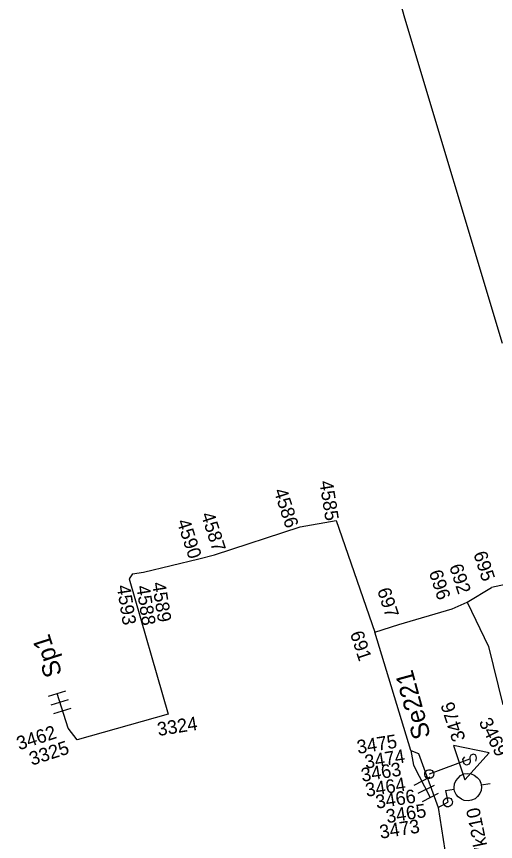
# Model space of a CAD drawing. Extents: x -535557 to -534097, y -1142175 to -1136716.
# Drawn here: x -534510.79 to -534484.36, y -1140790.82 to -1140745.31 of the extents above; entities that cross this region are included whole.
import ezdxf

# ---------------------------------------------------------------- set-up
doc = ezdxf.new("R2010")
doc.units = 0
doc.layers.add('Default', color=7, linetype='Continuous')
doc.layers.add('SS_SZDC', color=7, linetype='Continuous')

# ---------------------------------------------------------------- blocks, each defined once
blk = doc.blocks.new('POINT_DISPLAY')
at = {"layer": 'Default'}
blk.add_line((0, 0), (0, 0), dxfattribs=at)

msp = doc.modelspace()

# ---------------------------------------------------------------- linework, layer by layer
at = {"layer": 'SS_SZDC'}
for p, q in [((-534491.92, -1140736.569), (-534489.38, -1140745.379)), ((-534489.38, -1140745.379), (-534484, -1140763.329)), ((-534495.149, -1140773.459), (-534493.149, -1140773.12)), ((-534493.149, -1140773.12), (-534491.02, -1140779.27)), ((-534499.859, -1140775.01), (-534495.149, -1140773.459)), ((-534503.779, -1140775.959), (-534500.739, -1140775.239)), ((-534500.739, -1140775.239), (-534499.859, -1140775.01)), ((-534504.399, -1140776.049), (-534504.569, -1140776.34)), ((-534504.569, -1140776.34), (-534502.43, -1140783.809)), ((-534504.399, -1140776.049), (-534503.779, -1140775.959)), ((-534481.75, -1140776.209), (-534484.59, -1140776.819)), ((-534485.92, -1140777.629), (-534484.59, -1140776.819)), ((-534486.76, -1140777.989), (-534485.92, -1140777.629)), ((-534485.92, -1140777.629), (-534484.739, -1140780.069)), ((-534489.699, -1140778.86), (-534486.76, -1140777.989)), ((-534491.02, -1140779.27), (-534489.699, -1140778.86)), ((-534489.039, -1140785.809), (-534491.02, -1140779.27)), ((-534484.739, -1140780.069), (-534483.949, -1140783.28)), ((-534509.027, -1140782.812), (-534508.073, -1140782.512)), ((-534507.949, -1140784.569), (-534508.55, -1140782.662)), ((-534508.877, -1140783.289), (-534507.923, -1140782.989)), ((-534508.727, -1140783.766), (-534507.773, -1140783.466)), ((-534502.43, -1140783.809), (-534507.439, -1140785.219)), ((-534507.439, -1140785.219), (-534507.949, -1140784.569)), ((-534489.039, -1140785.809), (-534488.88, -1140786.62)), ((-534489.039, -1140785.809), (-534488.609, -1140785.979)), ((-534486.679, -1140785.524), (-534486.061, -1140787.426)), ((-534484.706, -1140785.934), (-534486.679, -1140785.524)), ((-534488.609, -1140785.979), (-534487.529, -1140788.94)), ((-534485.8, -1140786.29), (-534488.02, -1140787.11)), ((-534486.163, -1140786.303), (-534486.131, -1140786.24)), ((-534486.086, -1140786.54), (-534486.163, -1140786.303)), ((-534486.131, -1140786.24), (-534486.052, -1140786.161)), ((-534486.061, -1140787.426), (-534484.706, -1140785.934)), ((-534485.719, -1140786.053), (-534485.783, -1140786.179)), ((-534485.783, -1140786.179), (-534485.753, -1140786.432)), ((-534485.576, -1140786.007), (-534485.719, -1140786.053)), ((-534485.45, -1140786.071), (-534485.576, -1140786.007)), ((-534485.452, -1140786.387), (-534485.42, -1140786.324)), ((-534485.404, -1140786.213), (-534485.45, -1140786.071)), ((-534485.42, -1140786.324), (-534485.404, -1140786.213)), ((-534488.88, -1140786.62), (-534487.972, -1140788.402)), ((-534485.96, -1140786.605), (-534486.086, -1140786.54)), ((-534485.817, -1140786.558), (-534485.96, -1140786.605)), ((-534485.753, -1140786.432), (-534485.817, -1140786.558)), ((-534487.98, -1140787.284), (-534488.871, -1140787.738)), ((-534488.266, -1140787.152), (-534488.265, -1140787.041)), ((-534488.244, -1140787.22), (-534488.266, -1140787.152)), ((-534488.265, -1140787.041), (-534488.22, -1140786.951)), ((-534488.178, -1140787.31), (-534488.244, -1140787.22)), ((-534488.22, -1140786.951), (-534488.13, -1140786.885)), ((-534488.13, -1140786.885), (-534488.062, -1140786.863)), ((-534488.062, -1140786.863), (-534487.951, -1140786.864)), ((-534487.951, -1140786.864), (-534487.861, -1140786.909)), ((-534487.819, -1140787.268), (-534487.909, -1140787.334)), ((-534487.861, -1140786.909), (-534487.795, -1140786.999)), ((-534487.774, -1140787.178), (-534487.819, -1140787.268)), ((-534487.795, -1140786.999), (-534487.773, -1140787.067)), ((-534487.773, -1140787.067), (-534487.774, -1140787.178)), ((-534486.558, -1140787.473), (-534486.301, -1140787.18)), ((-534486.301, -1140787.18), (-534486.111, -1140787.099)), ((-534486.111, -1140787.099), (-534485.913, -1140787.068)), ((-534485.913, -1140787.068), (-534485.708, -1140787.086)), ((-534485.708, -1140787.086), (-534485.544, -1140787.161)), ((-534485.544, -1140787.161), (-534485.373, -1140787.286)), ((-534485.373, -1140787.286), (-534485.25, -1140787.418)), ((-534487.753, -1140787.729), (-534488.644, -1140788.183)), ((-534488.088, -1140787.355), (-534488.178, -1140787.31)), ((-534487.977, -1140787.356), (-534488.088, -1140787.355)), ((-534487.909, -1140787.334), (-534487.977, -1140787.356)), ((-534486.651, -1140787.843), (-534486.633, -1140787.637)), ((-534486.633, -1140787.637), (-534486.558, -1140787.473)), ((-534485.25, -1140787.418), (-534485.17, -1140787.608)), ((-534485.17, -1140787.608), (-534485.138, -1140787.805)), ((-534485.154, -1140787.707), (-534484.66, -1140787.628)), ((-534487.526, -1140788.175), (-534488.417, -1140788.629)), ((-534487.13, -1140788.02), (-534486.636, -1140787.941)), ((-534487.13, -1140788.02), (-534486.989, -1140788.659)), ((-534486.636, -1140787.941), (-534486.651, -1140787.843)), ((-534486.62, -1140788.04), (-534486.636, -1140787.941)), ((-534486.539, -1140788.23), (-534486.62, -1140788.04)), ((-534485.232, -1140788.175), (-534485.357, -1140788.346)), ((-534485.157, -1140788.011), (-534485.232, -1140788.175)), ((-534485.138, -1140787.805), (-534485.157, -1140788.011)), ((-534487.236, -1140788.702), (-534487.235, -1140788.591)), ((-534487.235, -1140788.591), (-534487.19, -1140788.501)), ((-534487.19, -1140788.501), (-534487.1, -1140788.435)), ((-534487.1, -1140788.435), (-534487.032, -1140788.413)), ((-534487.032, -1140788.413), (-534486.921, -1140788.414)), ((-534486.921, -1140788.414), (-534486.831, -1140788.459)), ((-534486.831, -1140788.459), (-534486.765, -1140788.549)), ((-534486.765, -1140788.549), (-534486.743, -1140788.617)), ((-534486.743, -1140788.617), (-534486.744, -1140788.728)), ((-534486.417, -1140788.362), (-534486.539, -1140788.23)), ((-534486.245, -1140788.487), (-534486.417, -1140788.362)), ((-534486.082, -1140788.562), (-534486.245, -1140788.487)), ((-534485.876, -1140788.58), (-534486.082, -1140788.562)), ((-534485.679, -1140788.549), (-534485.876, -1140788.58)), ((-534485.489, -1140788.468), (-534485.679, -1140788.549)), ((-534485.357, -1140788.346), (-534485.489, -1140788.468)), ((-534487.529, -1140788.94), (-534486.989, -1140788.659)), ((-534487.529, -1140788.94), (-534486.81, -1140793.44)), ((-534487.214, -1140788.77), (-534487.236, -1140788.702)), ((-534487.148, -1140788.86), (-534487.214, -1140788.77)), ((-534487.058, -1140788.905), (-534487.148, -1140788.86)), ((-534486.947, -1140788.906), (-534487.058, -1140788.905)), ((-534486.879, -1140788.884), (-534486.947, -1140788.906)), ((-534486.789, -1140788.818), (-534486.879, -1140788.884)), ((-534486.744, -1140788.728), (-534486.789, -1140788.818))]:
    msp.add_line(p, q, dxfattribs=at)

# ---------------------------------------------------------------- block references
for p in [(-534489.38, -1140745.379), (-534493.149, -1140773.12), (-534495.149, -1140773.459), (-534500.739, -1140775.239), (-534499.859, -1140775.01), (-534504.569, -1140776.34), (-534504.399, -1140776.049), (-534503.779, -1140775.959), (-534484.59, -1140776.819), (-534485.92, -1140777.629), (-534486.76, -1140777.989), (-534489.699, -1140778.86), (-534491.02, -1140779.27), (-534484.739, -1140780.069), (-534502.43, -1140783.809), (-534507.949, -1140784.569), (-534507.439, -1140785.219), (-534489.039, -1140785.809), (-534488.609, -1140785.979), (-534485.8, -1140786.29), (-534488.88, -1140786.62), (-534488.02, -1140787.11), (-534488.02, -1140787.11), (-534487.13, -1140788.02), (-534487.529, -1140788.94), (-534486.989, -1140788.659), (-534486.989, -1140788.659)]:
    msp.add_blockref('POINT_DISPLAY', p, dxfattribs=at)

# ---------------------------------------------------------------- texts
for s, height, rotation, p in [('4585', 0.75, 279, (-534494.084, -1140770.97)), ('4586', 0.75, 288, (-534496.608, -1140771.475)), ('4590', 0.75, 288, (-534501.957, -1140773.171)), ('4587', 0.75, 288, (-534500.625, -1140772.787)), ('695', 0.75, 288, (-534485.593, -1140774.944)), ('696', 0.75, 288, (-534488.049, -1140775.973)), ('692', 0.75, 288, (-534486.926, -1140775.646)), ('4593', 0.75, 279, (-534505.265, -1140776.726)), ('4588', 0.75, 279, (-534504.19, -1140776.749)), ('4589', 0.75, 279, (-534503.321, -1140776.566)), ('697', 0.75, 288, (-534490.902, -1140776.956)), ('Sp1', 1, 108, (-534508.259, -1140781.581)), ('691', 0.75, 288, (-534492.399, -1140779.341)), ('Se221', 1, 105.3, (-534487.932, -1140785.025)), ('3476', 0.75, 108, (-534486.004, -1140785.173)), ('3324', 0.75, 9, (-534502.968, -1140785.009)), ('3469', 0.75, 297, (-534485.305, -1140784.23)), ('3462', 0.75, 18, (-534510.648, -1140785.797)), ('3475', 0.75, 9, (-534491.954, -1140785.993)), ('3325', 0.75, 18, (-534509.947, -1140786.644)), ('3474', 0.75, 9, (-534491.521, -1140786.81)), ('3463', 0.75, 9, (-534491.72, -1140787.534)), ('3464', 0.75, 9, (-534491.48, -1140788.361)), ('3466', 0.75, 9, (-534490.923, -1140789.019)), ('3465', 0.75, 9, (-534490.345, -1140789.817)), ('Vk210', 0.75, 101.7, (-534484.684, -1140791.686)), ('3473', 0.75, 9, (-534490.704, -1140790.677))]:
    msp.add_text(s, height=height, rotation=rotation, dxfattribs=at).set_placement(p)

doc.saveas('drawing.dxf')
